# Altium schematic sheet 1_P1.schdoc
size 307 x 218 mm; Symbol: Drawing-Symbol_A4; Device: Drawing-Symbol_A4; @Project Name: Hacker Card; @Page Count: 1; @Update Date: 2025-07-18; @Create Date: 2025-07-18; @Schematic Name: Schematic1; @Page No: 1; @Page Name: P1; Company: EasyEDA.com; Version: V1.0; Page Size: A4; @Create Time: 10:57:28; @Update Time: 11:33:19; Width: 1170; Height: 825; Region Start: 1; X Region Count: 6; Y Region Count: 4; Blade Width: 10; Title Block Position: 3; @Board Name: Board1
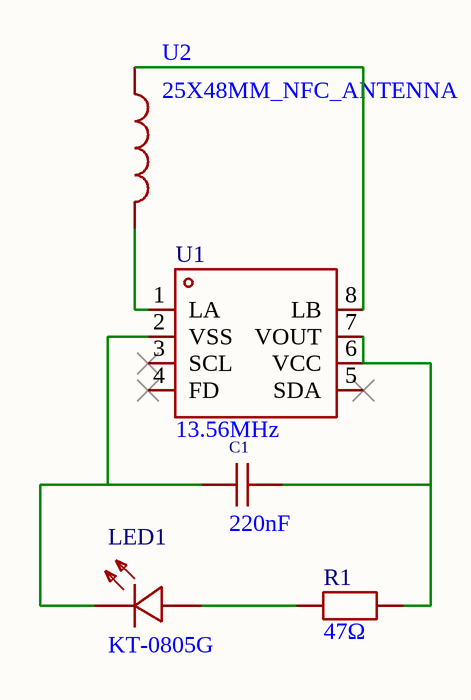
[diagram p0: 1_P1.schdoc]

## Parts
C1  220nF  [C0805]
LED1  KT-0805G  [LED0805-R-RD]
R1  47Ω  [R0805]
U1  13.56MHz  [SO-8_L4.9-W3.9-P1.27-LS6.0-BL]
U2  25X48MM_NFC_ANTENNA  [25X48MM_NFC_ANTENNA]

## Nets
NetC1_1: C1.1 LED1.2(K) U1.2(VSS)
NetC1_2: C1.2 R1.2 U1.6(VCC) U1.7(VOUT)
NetLED1_1: LED1.1(A) R1.1
NetU1_1: U1.1(LA) U2.P$2
NetU1_8: U1.8(LB) U2.P$1

Not connected (* = marked no-connect by the designer): U1 3(SCL)* 4(FD)* 5(SDA)*

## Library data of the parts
C1 = CL21B224KBFNNNE: Manufacturer: SAMSUNG(三星); Add into BOM: yes; Tolerance: ±10%
LED1 = KT-0805G: Manufacturer: KENTO; Symbol: 0805G (Green); Add into BOM: yes; Emitted Color: Emerald
R1 = FRC0805J470 TS: Manufacturer: FOJAN(富捷); Add into BOM: yes; Tolerance: ±5%; Power(Watts): 125mW; Voltage-Supply(Max): 150V; Temperature Coefficient: ±100ppm/℃
U1 = NT3H2111W0FHKH: Manufacturer: NXP(恩智浦); Add into BOM: yes; agreement: ISO 14443; interface type: I2C; mains input: 3.3V
U2 = 25X48MM_NFC_ANTENNA: Add into BOM: yes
